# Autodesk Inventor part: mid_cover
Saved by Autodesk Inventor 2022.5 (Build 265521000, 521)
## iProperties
Created: 2024-12
Part Number: mid_cover
Material: Generic
Document SubType Name: Modeling
Designer: AdminForWorker
Density: 1 g/cm^3
Appearance: Default
Title: mid_cover
Author: AdminForWorker
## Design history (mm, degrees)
feature "Body1"
body "Solid1"
